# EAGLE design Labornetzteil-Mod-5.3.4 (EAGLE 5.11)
OC_FARNELL: 0V
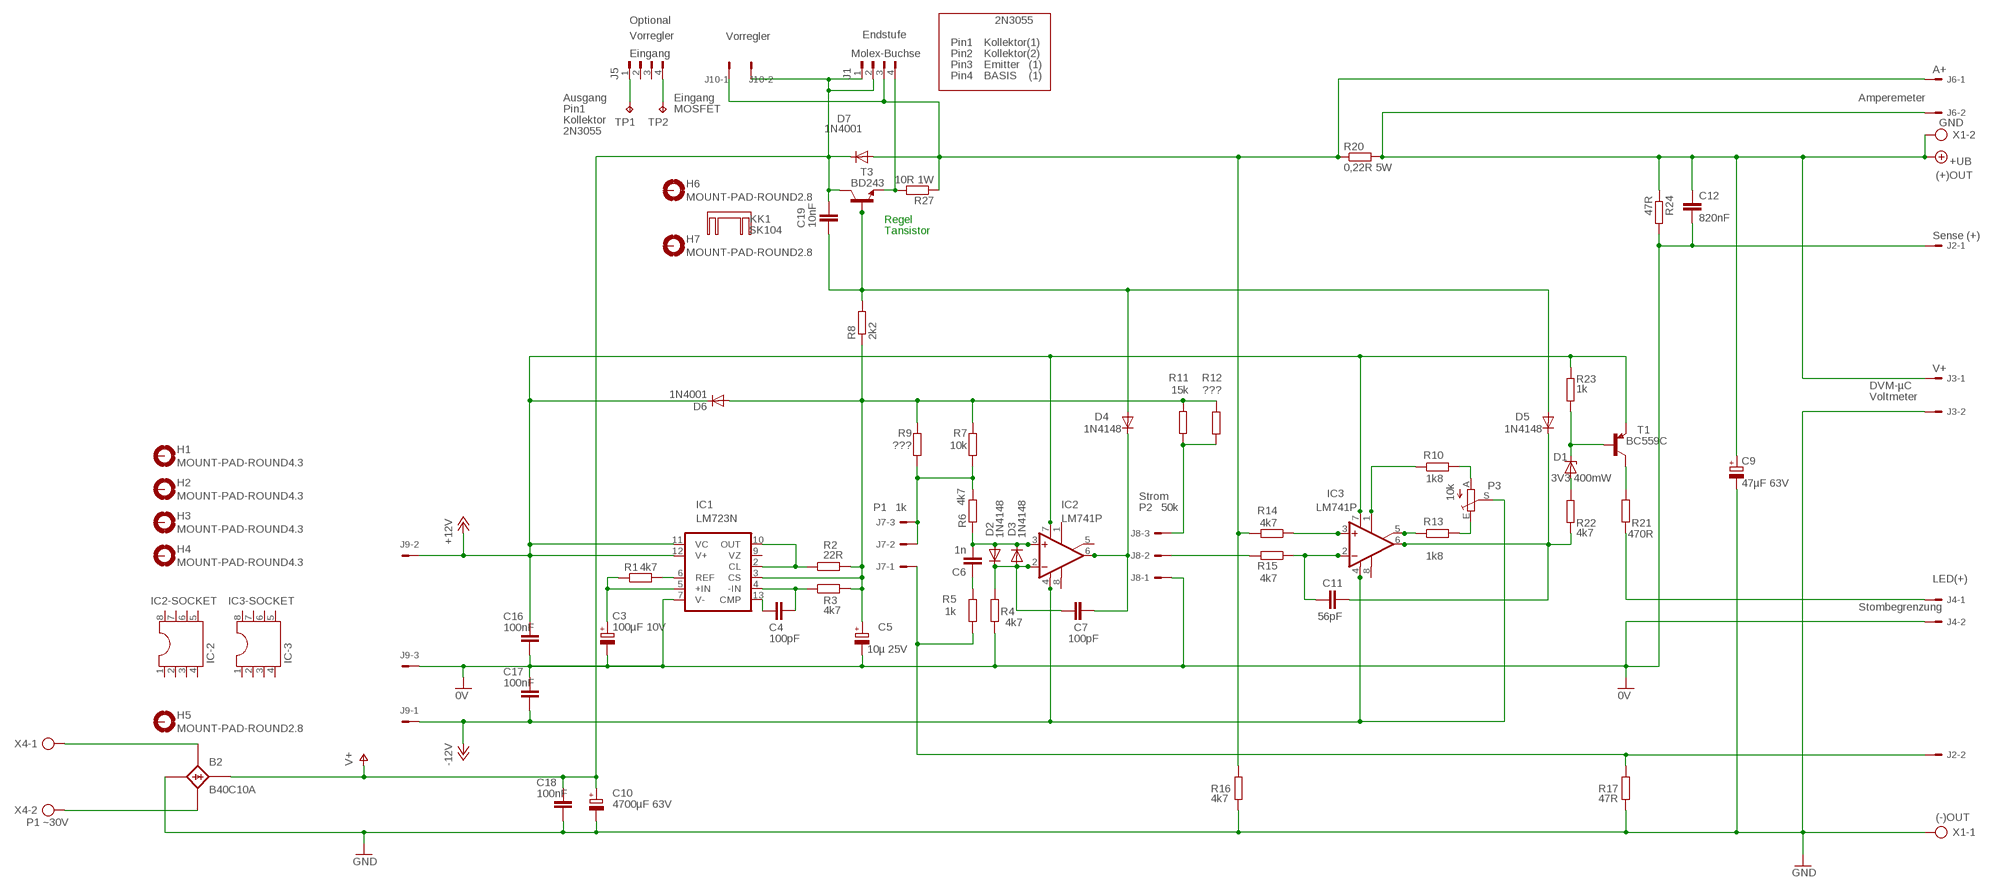
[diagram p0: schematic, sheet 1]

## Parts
B2  B40C10A  B25A-  [B25A-]
C3  100µF 10V  CPOL-EUE5-8.5  [E5-8,5]
C4  100pF  C-EU025-024X044  [C025-024X044]
C5  10µ 25V  CPOL-EUE5-8.5  [E5-8,5]
C6  1n  C-EU025-024X044  [C025-024X044]
C7  100pF  C-EU025-024X044  [C025-024X044]
C9  47µF 63V  CPOL-EUE3.5-8  [E3,5-8]
C10  4700µF 63V  CPOL-EUE10-35  [EB35D]
C11  56pF  C-EU025-024X044  [C025-024X044]
C12  820nF  C-EU025-024X044  [C025-024X044]
C16  100nF  C-EU025-030X050  [C025-030X050]
C17  100nF  C-EU025-030X050  [C025-030X050]
C18  100nF  C-EU025-030X050  [C025-030X050]
C19  10nF  C-EU025-024X044  [C025-024X044]
D1  3V3 400mW  ZENER-DIODEDO34-7  [DO34Z7]
D2  1N4148  1N4148DO35-10  [DO35-10]
D3  1N4148  1N4148DO35-10  [DO35-10]
D4  1N4148  1N4148DO35-10  [DO35-10]
D5  1N4148  1N4148DO35-10  [DO35-10]
D6  1N4001  1N4004  [DO41-10]
D7  1N4001  1N4004  [DO41-10]
H1  MOUNT-PAD-ROUND4.3  [4,3-PAD]
H2  MOUNT-PAD-ROUND4.3  [4,3-PAD]
H3  MOUNT-PAD-ROUND4.3  [4,3-PAD]
H4  MOUNT-PAD-ROUND4.3  [4,3-PAD]
H5  MOUNT-PAD-ROUND2.8  [2,8-PAD]
H6  MOUNT-PAD-ROUND2.8  [2,8-PAD]
H7  MOUNT-PAD-ROUND2.8  [2,8-PAD]
IC1  LM723N  [DIL14]
IC2  LM741P  [DIL08]
IC2-SOCKET  IC-2  DIL8S  [SOCKET-08]
IC3  LM741P  [DIL08]
IC3-SOCKET  IC-3  DIL8S  [SOCKET-08]
J1  Endstufe  FLOPPY-4  [FLOPPY-4]
J2  Sense (+)  22-27-2021-02  [6410-02]
J3  V+  22-27-2021-02  [6410-02]
J4  LED(+)  22-27-2021-02  [6410-02]
J5  Vorregler  FLOPPY-4  [FLOPPY-4]
J6  A+  22-27-2021-02  [6410-02]
J7  Spannung  22-27-2031-03  [6410-03]
J8  Strom  22-27-2031-03  [6410-03]
J9  -12V  22-27-2031-03  [6410-03]
J10  Vorregler  22-27-2021-02  [6410-02]
KK1  SK104  [SK104]
P3  10k  TRIM_EU-CA6V  [CA6V]
R1  4k7  R-EU_0204/2V  [0204V]
R2  22R  R-EU_0204/2V  [0204V]
R3  4k7  R-EU_0204/2V  [0204V]
R4  4k7  R-EU_0207/10  [0207/10]
R5  1k  R-EU_0207/10  [0207/10]
R6  4k7  R-EU_0207/10  [0207/10]
R7  10k  R-EU_0207/10  [0207/10]
R8  2k2  R-EU_0207/10  [0207/10]
R9  ???  R-EU_0207/10  [0207/10]
R10  1k8  R-EU_0207/10  [0207/10]
R11  15k  R-EU_0207/10  [0207/10]
R12  ???  R-EU_0207/10  [0207/10]
R13  1k8  R-EU_0207/10  [0207/10]
R14  4k7  R-EU_0207/10  [0207/10]
R15  4k7  R-EU_0207/10  [0207/10]
R16  4k7  R-EU_0207/10  [0207/10]
R17  47R  R-EU_0207/10  [0207/10]
R20  0,22R 5W  R-EU_0617/22  [0617/22]
R21  470R  R-EU_0207/10  [0207/10]
R22  4k7  R-EU_0207/10  [0207/10]
R23  1k  R-EU_0207/10  [0207/10]
R24  47R  R-EU_0207/10  [0207/10]
R27  10R 1W  R-EU_0613/15  [P0613/15]
T1  BC559C  -PNP-TO92  [TO92]
T3  BD243  2SC1307  [TO220AV]
TP1  TPPAD1-20Y  [P1-20Y]
TP2  TPPAD1-20Y  [P1-20Y]
X1  GND  AK300/2  [AK300/2]
X4  P1 ~30V  AK300/2  [AK300/2]

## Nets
0V: C3.- C5.- C12.2 C16.1 C17.2 IC1.7(V-) J2.1 J4.2 J8.1 J9.3 R4.1 R24.2
+12V: C16.2 D6.C IC1.11(VC) IC1.12(V+) IC2.7(V+) IC3.7(V+) J9.2 R23.1 T1.1(E)
+UB: C9.+ C12.1 J3.1 J6.2 R20.2 R24.1 X1.2
-12V: C17.1 IC2.4(V-) IC3.4(V-) J9.1 P3.S
-SENSE: J2.2 J7.1 R5.1 R17.1
GND: B2.-1(-) C9.- C10.- C18.1 J3.2 R16.2 R17.2 X1.1
N$1: C3.+ IC1.5(+IN) R1.1
N$5: IC1.6(REF) R1.2
N$7: C6.1 R5.2
N$8: J7.2 J7.3 R6.2 R7.1 R9.1
N$9: IC1.2(CL) IC1.10(OUT) R2.1
N$10: C4.2 IC1.4(-IN) R3.1
N$11: J5.1 TP1.TP
N$12: C4.1 IC1.13(CMP)
N$13: J4.1 R21.1
N$14: C5.+ D6.A IC1.3(CS) R2.2 R3.2 R7.2 R8.1 R9.2 R11.2 R12.1
N$15: C6.2 D2.A D3.C IC2.3(+IN) R6.1
N$16: C7.1 D2.C D3.A IC2.2(-IN) R4.2
N$17: C19.1 D4.A D5.A R8.2 T3.1(B)
N$18: C7.2 D4.C IC2.6(OUT)
N$19: J8.3 R11.1 R12.2
N$21: R21.2 T1.3(C)
N$22: IC3.3(+IN) R14.1
N$23: D1.C R23.2 T1.2(B)
N$24: J8.2 R15.2
N$25: D1.A R22.1
N$26: J5.4 TP2.TP
N$27: D7.A J1.3 J6.1 J10.1 R14.2 R16.1 R20.1 R27.1
N$30: IC3.5(ON2) R13.1
N$31: B2.AC1-(AC1) X4.1
N$32: B2.AC2-(AC2) X4.2
N$33: C11.1 IC3.2(-IN) R15.1
N$34: C11.2 D5.C IC3.6(OUT) R22.2
N$36: IC3.1(ON1) R10.1
N$42: J1.4 R27.2 T3.3(E)
N$43: P3.E R13.2
N$44: P3.A R10.2
V+: B2.+1(+) C10.+ C18.2 C19.2 D7.C J1.1 J1.2 J10.2 T3.2(C)
Unconnected: B2.+ B2.- B2.AC1 B2.AC2 H1.B4,3(MOUNT) H2.B4,3(MOUNT) H3.B4,3(MOUNT) H4.B4,3(MOUNT) H5.B2,8(MOUNT) H6.B2,8(MOUNT) H7.B2,8(MOUNT) IC1.9(VZ) IC2-SOCKET.1 IC2-SOCKET.2 IC2-SOCKET.3 IC2-SOCKET.4 IC2-SOCKET.5 IC2-SOCKET.6 IC2-SOCKET.7 IC2-SOCKET.8 IC2.1(ON1) IC2.5(ON2) IC2.8(OPT) IC3-SOCKET.1 IC3-SOCKET.2 IC3-SOCKET.3 IC3-SOCKET.4 IC3-SOCKET.5 IC3-SOCKET.6 IC3-SOCKET.7 IC3-SOCKET.8 IC3.8(OPT) J5.2 J5.3

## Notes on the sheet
- Optional | 2N3055
- Pin1 | Kollektor(1)
- Eingang | Molex-Buchse | Pin2 | Kollektor(2)
- Pin3 | Emitter   (1)
- Pin4 | BASIS    (1)
- Ausgang | Eingang | Amperemeter
- Pin1 | MOSFET
- Kollektor
- 2N3055
- (+)OUT
- Regel
- Tansistor
- DVM-µC
- Voltmeter
- Strom
- P1 | 1k | P2 | 50k
- Stombegrenzung
- (-)OUT

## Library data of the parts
B2 = rectifier:B25A-: RECTIFIER 25-A bridge
C3 C5 C9 C10 = rcl:CPOL-EU: POLARIZED CAPACITOR, European symbol
C4 C6 C7 C11 C12 C16-C19 = rcl:C-EU: CAPACITOR, European symbol
D1 = diode:ZENER-DIODE: Z-Diode
D2-D5 = diode:1N4148: DIODE
D6 D7 = diode:1N4004: DIODE
H1-H7 = holes:MOUNT-PAD-ROUND: MOUNTING PAD, round
IC1 = linear:*723: Positive VOLTAGE REGULATOR
IC2 IC3 = linear:*741: OP AMP
IC2-SOCKET IC3-SOCKET = ic-package:DIL8: Dual In Line / Socket
J1 J5 = con-amp:FLOPPY-4: MATE N-LOCK Floppy / HDD conector Distributor: Bürklin 71F970; OC_FARNELL: unknown; OC_NEWARK: unknown
J2-J4 J6 J10 = con-molex:22-?-02: CONNECTOR; OC_FARNELL: unknown; OC_NEWARK: unknown
J7-J9 = con-molex:22-?-03: CONNECTOR wire to board 2.54 mm (.1 inch) pitch header; OC_FARNELL: unknown; OC_NEWARK: unknown
KK1 = heatsink:SK104: HEATSINK
P3 = pot:TRIM_EU-: POTENTIOMETER
R1-R17 R20-R24 R27 = rcl:R-EU_: RESISTOR, European symbol
T1 = transistor:*-PNP-: PNP Transistror
T3 = transistor:2SC1307: NPN Transistor Silicon Epitaxial, High Frequency Power Amplifier Source: 2SC1307.pdf
TP1 TP2 = testpad:TP: Test pad
X1 X4 = con-ptr500:AK300/2: CONNECTOR; OC_FARNELL: unknown; OC_NEWARK: unknown

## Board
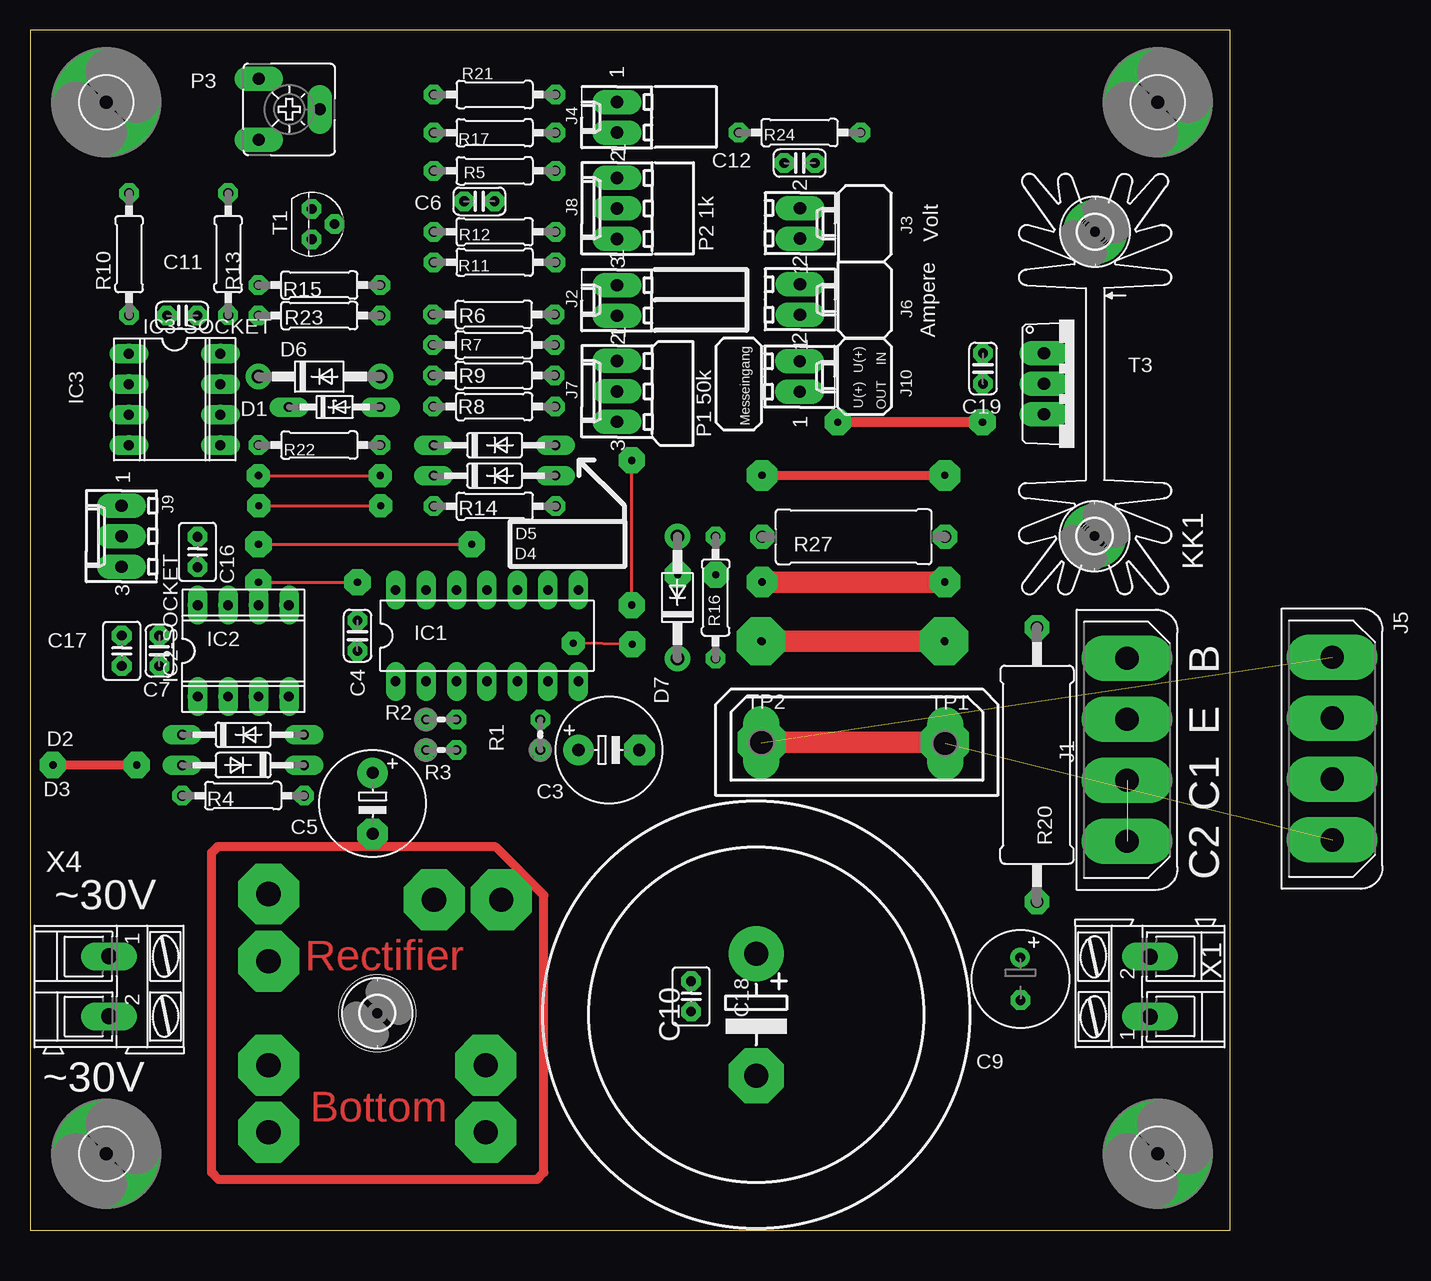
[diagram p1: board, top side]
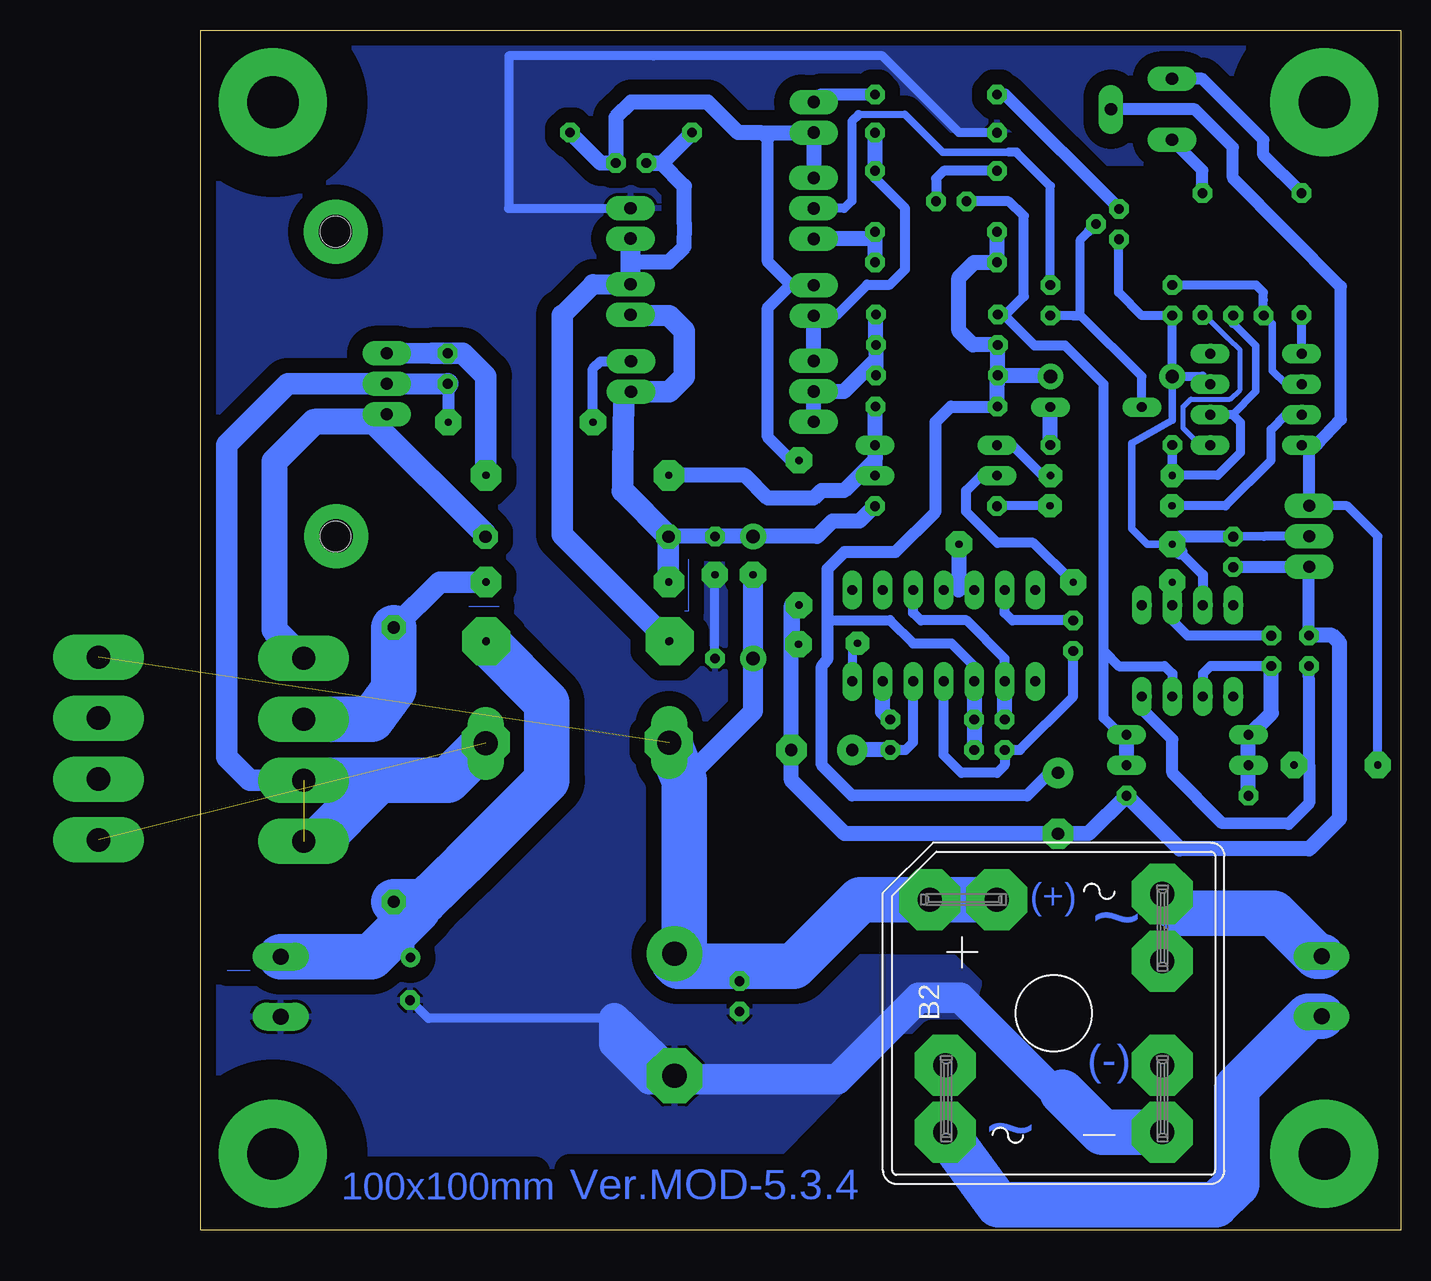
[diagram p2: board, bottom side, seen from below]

Size 100 x 100 mm. Coordinates in mm from the lower left corner, seen from the top.
Outline: 0,0 100,0 100,100 0,100 0,0
Copper layers (1*16): Top 0.035mm / dielectric 1.5mm / Bottom 0.035mm
Design rules "default *": minimum track width 30mil, minimum drill 24mil, track to track 8mil, track to pad 8mil, pad to pad 8mil, via to via 8mil, smd to smd 8mil, copper to edge 0.5mm, drill to drill 8mil, minimum pad ring 10mil, minimum via ring 8mil, stop-mask expansion 4mil, vias tented up to drill 0mil, thermal gap 10mil

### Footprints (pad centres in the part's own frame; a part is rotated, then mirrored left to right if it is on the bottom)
B25A- = drill 2.007 pad 5.08 octagon: + -10.338,9.449; +1 -4.75,9.449; - 9.042,-4.343; -1 9.042,-9.931; AC1 9.042,4.343; AC1- 9.042,9.931; AC2 -9.042,-4.343; AC2- -9.042,-9.931 | hole 6.401: 0,0
E5-8,5 = drill 1.016 pad 2.54 round: + -2.54,0 | drill 1.016 pad 2.54 octagon: - 2.54,0
C025-024X044 = drill 0.813 octagon: 1 -1.27,0; 2 1.27,0
E3,5-8 = drill 0.813 pad 1.6 round: + -1.778,0 | drill 0.813 pad 1.6 octagon: - 1.778,0
EB35D = drill 2.007 pad 4.597 round: + -5.08,0 | drill 2.007 pad 4.597 octagon: - 5.08,0
C025-030X050 = drill 0.813 octagon: 1 -1.27,0; 2 1.27,0
DO34Z7 = drill 0.813 long: A 3.81,0; C -3.81,0
DO35-10 = drill 0.813 long: A 5.08,0; C -5.08,0
DO41-10 = drill 1.118 round: A 5.08,0; C -5.08,0
4,3-PAD = drill 4.3 pad 9 round: B4,3 0,0
2,8-PAD = drill 2.8 pad 5.334 round: B2,8 0,0
DIL14 = drill 0.813 long: 1 -7.62,-3.81; 2 -5.08,-3.81; 3 -2.54,-3.81; 4 0,-3.81; 5 2.54,-3.81; 6 5.08,-3.81; 7 7.62,-3.81; 8 7.62,3.81; 9 5.08,3.81; 10 2.54,3.81; 11 0,3.81; 12 -2.54,3.81; 13 -5.08,3.81; 14 -7.62,3.81
DIL08 = drill 0.813 pad 1.27 round: 1 -3.81,-3.81; 2 -1.27,-3.81; 3 1.27,-3.81; 4 3.81,-3.81; 5 3.81,3.81; 6 1.27,3.81; 7 -1.27,3.81; 8 -3.81,3.81
SOCKET-08 = drill 0.813 long: 1 -3.81,-3.81; 2 -1.27,-3.81; 3 1.27,-3.81; 4 3.81,-3.81; 5 3.81,3.81; 6 1.27,3.81; 7 -1.27,3.81; 8 -3.81,3.81
FLOPPY-4 = drill 1.93 pad 3.81 long: 1 7.62,0; 2 2.54,0; 3 -2.54,0; 4 -7.62,0
6410-02 = drill 1.016 long: 1 1.27,0; 2 -1.27,0
6410-03 = drill 1.016 long: 1 2.54,0; 2 0,0; 3 -2.54,0
SK104 = hole 2.54: -12.7,-0.762; 12.7,-0.762
CA6V = drill 1.016 long: A -2.54,-2.54; E 2.54,-2.54; S 0,2.54
0204V = drill 0.813 octagon: 1 -1.27,0; 2 1.27,0
0207/10 = drill 0.813 octagon: 1 -5.08,0; 2 5.08,0
0617/22 = drill 1.016 octagon: 1 -11.43,0; 2 11.43,0
P0613/15 = drill 1.016 octagon: 1 -7.62,0; 2 7.62,0
TO92 = drill 0.813 octagon: 1 1.27,0; 2 0,1.905; 3 -1.27,0
TO220AV = drill 1.016 long: 1 -2.54,-2.54; 2 0,-2.54; 3 2.54,-2.54
P1-20Y = drill 2.007 pad 2.54 long: TP 0,0
AK300/2 = drill 1.321 long: 1 -2.515,0; 2 2.489,0

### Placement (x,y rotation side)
B2  28.92,18.07 0 bottom
C3  48.24,40.01 0 top
C4  27.29,49.53 270 top
C5  28.55,35.56 270 top
C6  37.45,85.72 180 top
C7  10.78,48.26 90 top
C9  82.53,20.93 270.5 top
C10  60.51,17.94 270 top
C11  12.68,76.2 0 top
C12  64.13,88.92 0 top
C16  13.96,56.51 90 top
C17  7.65,48.26 90 top
C18  55.09,19.47 90 top
C19  79.41,71.79 270 top
D1  25.38,68.58 0 top
D2  17.76,41.27 0 top
D3  17.76,38.73 180 top
D4  38.72,62.87 0 top
D5  38.72,65.41 0 top
D6  24.11,71.12 0 top
D7  53.96,52.7 90 top
H1  6.35,93.98 0 top
H2  6.35,6.35 0 top
H3  93.98,93.98 0 top
H4  93.98,6.35 0 top
H5  28.94,18.07 0 top
H6  88.75,83.19 0 top
H7  88.71,57.82 0 top
IC1  38.08,49.53 0 top
IC2  17.76,48.26 0 top
IC2-SOCKET  17.78,48.26 0 top
IC3  12.05,69.22 270 top
IC3-SOCKET  12.06,69.22 270 top
J1  91.42,40.01 270 top
J2  48.91,77.47 90 top
J3  64.17,83.89 270 top
J4  48.91,92.73 90 top
J5  not placed on the board
J6  64.17,77.55 270 top
J7  48.92,69.88 90 top
J8  48.92,85.13 90 top
J9  7.62,57.81 90 top
J10  64.14,71.12 270 top
KK1  89.51,70.49 270 top
P3  21.6,93.39 270 top
R1  42.53,41.27 90 top
R2  34.27,42.55 0 top
R3  34.27,40.01 0 top
R4  17.76,36.2 180 top
R5  38.72,88.27 180 top
R6  38.65,76.3 0 top
R7  38.65,73.76 180 top
R8  38.68,68.62 0 top
R9  38.65,71.22 180 top
R10  8.26,81.32 90 top
R11  38.72,80.64 180 top
R12  38.72,83.19 0 top
R13  16.52,81.32 90 top
R14  38.72,60.31 0 top
R15  24.11,78.74 0 top
R16  57.13,52.7 270 top
R17  38.72,91.44 180 top
R20  83.91,38.78 270 top
R21  38.72,94.61 180 top
R22  24.11,65.41 180 top
R23  24.11,76.2 0 top
R24  64.13,91.46 0 top
R27  68.64,57.77 0 top
T1  23.48,83.82 270 top
T3  87.04,70.52 270 top
TP1  76.26,40.55 0 top
TP2  60.95,40.62 0 top
X1  93.33,20.29 90 top
X4  6.59,20.29 270 top

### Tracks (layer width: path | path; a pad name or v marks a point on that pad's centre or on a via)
0V  (via drill 0.61 pad 1.93, 0.61 pad 2.18)
  Top 0.254: v50.15,52.07 v50.15,64.14 | v50.19,48.81 v45.27,48.9
  Bottom 0.254: v50.19,48.81 50.19,50.12 v50.15,52.07
  Bottom 0.762: IC1.7 45.7,48.51 v45.27,48.9
  Bottom 1.016: 50.78,52.08 v50.15,52.07 | 48.92,91.48 48.88,91.48 J4.2 | 53.34,91.46 52.73,90.85 52.73,80.68 50.79,78.74 J2.1 50.86,78.74 52.73,76.87 52.73,66.07 50.19,63.53 50.19,63.54 v50.15,64.14 | C17.2 7.65,55.25 | 7.65,55.25 J9.3 | 7.65,55.25 13.95,55.25 C16.1
  Bottom 1.27: 50.78,52.08 C3.- 50.78,37.47 46.34,33.02 C5.- 26.02,33.02 R4.1 22.84,36.18 18.42,31.77 7.62,31.77 5.08,34.31 5.08,48.92 5.72,49.55 7.63,49.55 C17.2 | J4.2 53.34,91.46 55.21,91.46 57.73,93.98 64.14,93.98 65.4,92.71 C12.2 66.67,88.92 R24.2 | 48.92,91.48 J8.1
+12V  (via drill 0.61 pad 2.18)
  Top 0.254: v19.03,57.15 v36.81,57.15
  Bottom 0.61: v19.03,57.15 21.13,57.15 22.4,58.42 22.4,65.57 19.03,67.49 D6.C
  Bottom 0.762: T1.1 23.51,82.52 23.51,78.14 21.57,76.2 R23.1 D6.C 19,71.15 16.52,71.15 15.86,70.49 IC3.7 | C16.2 11.38,57.81 J9.2 | v19.03,57.15 17.75,55.87
  Bottom 0.813: IC1.12 36.85,53.34 IC1.11 | IC2.7 16.49,54.61 v19.03,57.15
  Bottom 1.016: C16.2 18.41,57.77 v19.03,57.15
  Bottom 1.27: v19.03,57.15 18.4,56.52 | v36.81,57.15 36.81,53.38 36.85,53.34
+UB  (via drill 0.61 pad 2.18)
  Top 1.778: v76.24,49.04 v60.99,49.04
  Bottom 0.762: C9.+ 82.52,25.95 R20.2
  Bottom 1.27: J3.1 64.1,82.54 | 64.17,80.68 62.26,80.68 60.99,80.68 59.72,81.95 59.68,83.82 59.69,83.82 59.69,87 61.59,88.9 62.85,88.9 C12.1 61.59,88.92 R24.1
  Bottom 1.676: J3.1 64.17,80.68 J6.2 67.3,78.81 69.88,76.23
  Bottom 1.778: 69.88,76.23 69.88,57.95 v60.99,49.04
  Bottom 3.81: v76.24,49.04 71.18,43.96 71.15,37.48 78.06,30.58 81.32,27.4 R20.2 83.24,26.67 81.92,26.67 85.8,22.78 X1.2
-12V  (via drill 0.61 pad 2.18)
  Top 0.762: v1.91,38.75 v8.89,38.75
  Bottom 0.762: J9.1 4.45,60.35 1.91,57.81 v1.91,38.75 | v8.89,38.75 7.62,38.75
  Bottom 0.813: IC3.4 8.21,65.44
  Bottom 1.016: IC2.4 21.57,43.42 19.03,40.88 19.03,38.1 14.88,33.9 9.35,33.85 7.62,35.58 7.62,38.75 7.62,45.11 C17.1 | IC3.4 8.23,65.41 7.62,64.8 J9.1 | 8.21,65.44 6.99,65.44 4.97,67.55 4.97,78.62 13.98,87.67 13.98,90.21 17.15,93.39 P3.S
-SENSE
  Bottom 0.762: 43.8,87.63 R5.1 | J2.2 48.87,76.24
  Bottom 0.813: 43.8,87.63 41.29,85.13 41.29,80.05 42.56,78.78 44.47,78.78 47.01,76.24 48.87,76.24
  Bottom 1.27: R5.1 R17.1 | J2.2 48.91,72.43 J7.1
GND  (via drill 0.61 pad 2.18)
  Bottom 0.762: R17.2 36.8,91.44 43.2,97.84 62.26,97.84 74.33,97.83 74.33,85.13 66.71,85.13 64.21,85.13 J3.2 | v57.15,54.61 57.15,47.64 R16.2 | 65.54,17.62 81.02,17.62 C9.-
  Bottom 2.54: 28.21,11.47 28.82,11.47 36.71,19.36 40.16,19.36 46.94,12.58 62.58,12.58 65.54,15.54 65.54,17.62 C10.-
  Bottom 3.81: B2.-1 24.88,8.14 28.21,11.47
  pour Bottom (isolate 1.27): -1.27,100.97 -1.27,88.9 31.75,88.9 31.98,37.47 31.98,37.32 37.47,31.84 37.47,31.8 47.18,22.8 37.23,22.71 33.1,18.65 33.14,16.55 41.76,16.55 52.82,5.17 101.96,5.43 101.71,101.24
N$1
  Bottom 0.813: IC1.5 40.62,40.64 41.26,40.01 R1.1
  Bottom 1.27: R1.1 C3.+
N$2
  Top 0.762: 15.58,31.93 38.79,31.93 42.83,27.89 42.83,4.79 42.26,4.23 15.71,4.23 15.14,4.79 15.14,31.46 15.6,31.91
N$5
  Bottom 1.27: R1.2 43.16,43.18 IC1.6
N$6  (via drill 0.61 pad 4)
  other vias: 60.91,49.08
N$7
  Bottom 0.813: C6.1 38.72,87.63 38.08,88.27 R5.2
N$8
  Bottom 0.762: 43.8,72.46 43.8,73.66
  Bottom 1.27: R7.1 43.73,73.73 43.8,73.66 | R7.1 R9.1 | R7.1 R6.2 | 43.8,72.46 46.38,69.88 J7.2 J7.3
N$9
  Bottom 0.813: IC1.10 40.62,51.44 39.99,50.8 36.18,50.8 33,47.62 IC1.2
  Bottom 1.27: R2.1 IC1.2
N$10
  Bottom 0.813: C4.2 27.29,44.45 31.73,40.01 R3.1 33,38.73 33.64,38.1 36.6,38.1 38.08,39.58 IC1.4
N$11  (1 unrouted)
N$12
  Bottom 0.813: C4.1 32.37,50.8 33,51.44 IC1.13
N$13
  Bottom 1.016: R21.1 48.29,94.61 J4.1
N$14
  Bottom 0.762: 29.29,71.22 D6.A | R8.1
  Bottom 0.813: IC1.3 35.54,46.99 37.45,48.9 40.64,48.9 42.56,50.82 47.75,50.82
  Bottom 1.016: C5.+ 29.22,38.12 31.13,36.21 45.7,36.2 48.24,38.73 48.24,46.99 47.75,47.62 47.75,50.82 47.75,55.1 46.34,56.52 42.1,56.52 38.75,59.87 38.75,67.34 37.48,68.61 R8.1
  Bottom 1.27: R3.2 R2.2 IC1.3 | R8.1 33.6,70.55 R9.2 | R9.2 R7.2 35.64,73.76 36.81,74.93 36.81,79.38 35.54,80.64 R11.2 R12.1 | R9.2 29.29,71.22
N$15
  Bottom 0.61: R6.1 32.9,76.3
  Bottom 0.762: 32.83,76.03 32.83,76.2
  Bottom 0.813: 33.74,76.3 R6.1 32.83,76.2 33,76.2 | IC2.3 19.03,46.35 19.67,46.99 23.48,46.99 24.75,48.26 | C6.2 32.68,85.72 31.41,84.51 31.41,77.79 32.9,76.3 | 22.84,40.77 24.75,42.67 24.75,48.26 | 24.75,48.26 24.75,70.49 27.95,73.69 30.49,73.69 32.83,76.03
  Bottom 1.27: D3.C 22.84,40.77 D2.A
N$16
  Bottom 0.813: IC2.2 16.49,46.35 15.86,46.99 C7.1
  Bottom 1.27: 12.68,41.17 D3.A R4.2 | 12.68,41.17 D2.C | 12.68,41.17 10.78,43.07 C7.1
N$17  (via drill 0.61 pad 2.54)
  Top 0.762: v60.99,62.9 v76.24,62.9
  Bottom 0.762: R8.2 43.76,67.98 | 83.89,73.03 84.47,73.03 T3.1
  Bottom 1.27: D4.A D5.A | D5.A 43.8,68.59 R8.2 | D5.A 43.8,64.2 46.38,61.62 48.28,61.62 48.92,60.99 52.73,60.99 54.64,62.9 v60.99,62.9
  Bottom 1.676: 83.89,73.03 C19.1 83.86,73.06 80.68,73.06
  Bottom 1.778: 80.68,73.06 78.14,73.06 76.24,71.15 v76.24,62.9
N$18  (via drill 0.61 pad 2.18)
  Top 0.254: v19.03,53.98 v27.29,53.98
  Bottom 0.61: 19.03,50.8 IC2.6
  Bottom 0.762: 34.97,62.87 D4.C
  Bottom 0.813: IC2.6 v19.03,53.98 | 19.03,50.8 17.76,49.53 C7.2 | 34.97,62.87 36.21,61.62 36.21,59.85 33.61,57.26 30.64,57.26 v27.29,53.98
N$19
  Bottom 1.27: R11.1 43.8,82.59 | 43.8,82.59 R12.2 | J8.3 43.8,82.59
N$20
  Bottom 3.81: 91.48,32.4 90.21,32.4 85.77,36.85
N$21
  Bottom 0.762: 32.99,94.61 R21.2 | 23.51,85.13 23.51,85.12 T1.3
  Bottom 1: 23.51,85.13 32.99,94.61
N$22  (via drill 0.61 pad 1.93)
  Top 0.254: v19.06,60.35 v29.22,60.35
  Bottom 0.762: R14.1 33.67,60.35 v29.22,60.35 | v19.06,60.35 14.61,60.35 10.8,64.17 10.8,66.71 9.53,67.98 8.27,67.98 IC3.3
N$23
  Bottom 0.762: 27.35,76.2 R23.2 | 26.68,76.24 27.35,76.2 | 26.68,76.24 26.68,82.52 26.02,83.19 | D1.C 21.57,71.12 26.68,76.24 | 26.68,76.24 26.68,76.17 27.35,76.2
  Bottom 0.813: T1.2 26.02,83.19
N$24
  Bottom 0.61: 45.18,92.94 41.32,92.97 38.16,89.83 32.66,89.83
  Bottom 0.762: J8.2 46.38,85.13 45.74,85.77 45.74,92.38 45.18,92.94 | R15.2 29.19,87 32.02,89.83 32.66,89.83
N$25
  Bottom 1.27: R22.1 D1.A
N$26  (1 unrouted)
N$27  (via drill 0.61 pad 2.54)
  Top 1.778: v60.99,54 v76.24,54
  Bottom 0.762: 60.97,57.81 57.16,57.81 R16.1 D7.A | J10.1 64.76,69.22
  Bottom 1.27: R14.2 43.88,60.31 45.11,59.08 47.37,59.08 48.64,57.81 60.97,57.81 R27.1
  Bottom 1.778: R27.1 61.02,54.03 v60.99,54 | v76.24,54 80.08,54 R20.1 | 64.81,61.6 64.81,63.52 64.76,69.22 64.75,69.87 60.96,69.85 59.69,71.12 59.69,74.93 60.96,76.2 64.8,76.23 64.22,76.23 J6.1
  Bottom 1.93: R27.1 64.81,61.6
  Bottom 3.81: J1.3 85.85,42.55 85.76,42.57 83.91,45.05 R20.1
N$30
  Bottom 0.406: IC3.5 16.73,65.43 18.12,66.82 18.12,68.61 17.49,69.25 14.2,69.25 13.38,70.03 13.38,73.32 14.39,74.27 16.16,76.05 16.48,76.05 R13.1
N$31
  Bottom 3.81: X4.1 7.01,22.8 10.6,26.39 18.14,26.39 B2.AC1-
N$32
  Bottom 3.81: X4.2 7.71,17.8 13.68,11.84 13.68,3.82 15.4,2.1 33.52,2.1 B2.AC2-
N$33
  Bottom 0.61: C11.1 11.37,76.2 10.71,75.54 10.71,71.61 9.54,70.48 IC3.2
  Bottom 0.762: R15.1 12.04,78.74 11.44,78.14 11.44,77.49 C11.1
N$34  (via drill 0.61 pad 1.93)
  Top 0.254: v19.03,62.87 v29.19,62.87
  Bottom 0.61: 14.01,67.94 12.07,69.88 12.07,73.7 13.98,75.6
  Bottom 0.762: v19.03,62.87 R22.2 19.03,62.92 19.06,62.9 15.25,62.9 13.34,64.8 13.34,67.28 14.01,67.94 IC3.6 | 33.01,65.41 D5.C 33.61,65.44 | 13.98,75.6 13.98,75.54 C11.2 | v29.19,62.87 29.83,62.87
  Bottom 0.813: 29.83,62.87 32.4,65.44 33.61,65.44
N$36
  Bottom 0.762: R10.1 8.24,76.24 IC3.1
N$38  (via drill 0.61 pad 4)
  other vias: 76.2,49.08
N$39
  Bottom 0: 59.31,55.88 59.31,51.58 59.67,51.56
N$40
  Bottom 0: 75.11,51.92 77.65,51.92
N$41
  Bottom 0: 95.89,21.59 97.79,21.59
N$42
  Bottom 0.762: 85.68,67.34 85.13,67.34 T3.3
  Bottom 1.93: R27.2 76.26,57.92 85.68,67.34
  Bottom 2.184: J1.4 91.42,47.59 93.86,50.03 93.86,64.02 90.54,67.34 85.68,67.34
N$43
  Bottom 1.016: R13.2 16.52,88.31 P3.E
N$44
  Bottom 1.016: P3.A 16.52,95.93 11.44,90.85 11.44,89.58 R10.2
V+  (via drill 0.61 pad 2.18, 0.61 pad 4)  (1 unrouted)
  Top 0.813: v79.38,67.31 v67.31,67.31
  Top 1.778: v60.99,40.66 v76.24,40.66
  Bottom 0.762: T3.2 80.05,70.52 C19.2 | C18.2 55.09,21.52 55.56,21.99
  Bottom 0.813: J10.2 66.67,72.39 67.31,71.75 v67.31,67.31
  Bottom 1.016: v79.38,67.31 79.38,69.85 C19.2
  Bottom 1.676: 59.72,37.48 53.96,43.25 D7.C 53.96,54.59 v53.98,54.61
  Bottom 1.778: C19.2 83.89,70.49 | J1.2 91.43,37.48 95.93,37.48 97.84,39.39 97.84,65.44 92.75,70.52 T3.2
  Bottom 3.81: J1.2 79.42,37.47 v76.24,40.66 | v60.99,40.66 59.72,37.48 59.71,22.92 C10.+ 60.59,22.94 60.59,22.32 60.26,21.99 55.56,21.99 50.57,21.99 45.04,27.52 B2.+1

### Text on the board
Top: Rectifier | Bottom
Bottom: (+) | ~ | (-) | ~ | Ver.MOD-5.3.4 | 100x100mm
tPlace: P2 1k | Volt | U(+) | Ampere | IN | U(+) | OUT | Messeingang | P1 50k
bOrigins: Ver.MOD-5.3.4 | 100x100mm | optional | Vorregler
tNames: B | E | C1 | ~30V | C2 | ~30V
